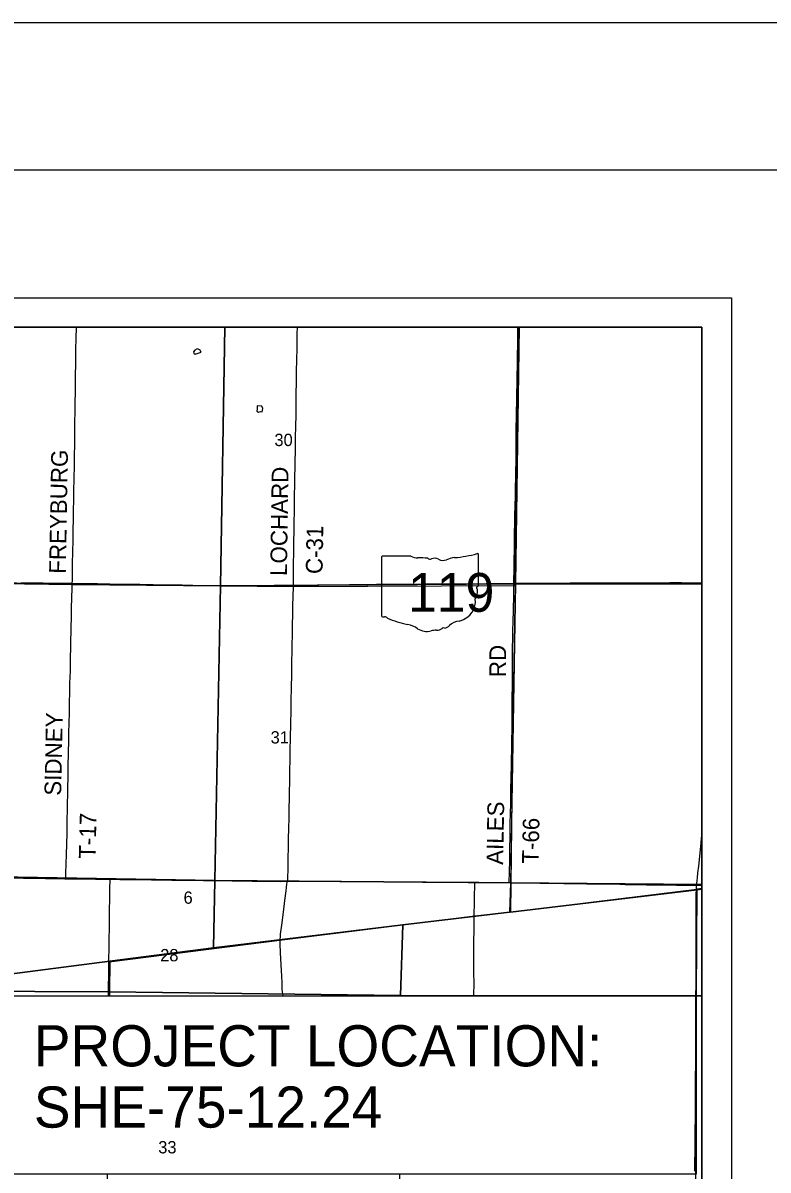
# Model space of a CAD drawing. Extents: x -784 to 1375, y -225 to 440.
# Drawn here: x 534 to 584.7, y 362 to 440 of the extents above; entities that cross this region are included whole.
import ezdxf

# ---------------------------------------------------------------- set-up
doc = ezdxf.new("R2010")
doc.units = 0
for name, color, linetype in [('GM_X_County_Road', 7, 'Continuous'), ('GM_X_County_Road_Text', 7, 'Continuous'), ('GM_X_Minor_Lake', 7, 'Continuous'), ('GM_X_Section', 7, 'Continuous'), ('GM_X_Section_Text', 7, 'Continuous'), ('GM_X_State_Location', 7, 'Continuous'), ('GM_X_State_Route', 7, 'Continuous'), ('GM_X_State_Shield', 7, 'Continuous'), ('GM_X_Township', 7, 'Continuous'), ('GM_X_Township_Road', 7, 'Continuous'), ('GM_X_Township_Road_Text', 7, 'Continuous'), ('SH_Border', 7, 'Continuous'), ('SH_Cut_Line', 7, 'Continuous'), ('SH_Data', 7, 'Continuous'), ('SH_Text', 7, 'Continuous')]:
    doc.layers.add(name, color=color, linetype=linetype)

msp = doc.modelspace()

# ---------------------------------------------------------------- linework, layer by layer
at = {"layer": 'GM_X_County_Road'}
for points in [[(552.435, 401.755), (552.433, 401.938), (552.43, 402.166), (552.431, 402.459), (552.441, 403.13), (552.456, 404.037), (552.467, 404.808), (552.476, 405.342), (552.488, 405.939), (552.499, 406.858), (552.505, 407.231), (552.513, 407.902), (552.525, 408.523), (552.532, 409.116), (552.542, 409.791), (552.554, 410.188), (552.564, 410.855), (552.567, 411.282), (552.58, 411.928), (552.59, 412.441), (552.606, 413.456), (552.613, 413.978), (552.627, 414.86), (552.633, 415.482), (552.641, 416.228), (552.646, 416.563), (552.653, 416.812), (552.663, 417.259), (552.674, 417.669), (552.676, 418.029), (552.689, 418.849), (552.699, 419.309)], [(579.873, 381.341), (579.883, 381.46), (579.906, 381.651), (579.922, 381.836), (579.963, 382.182), (580.011, 382.626), (580.154, 383.973), (580.212, 384.517), (580.236, 384.74)], [(539.873, 376.089), (539.876, 376.282), (539.883, 377.053), (539.89, 377.786), (539.902, 378.32), (539.911, 378.904), (539.92, 379.849), (539.927, 380.209), (539.942, 381.191), (539.948, 381.613), (539.95, 381.747)], [(579.851, 380.737), (579.857, 381.054), (579.87, 381.301), (579.873, 381.341)], [(579.873, 381.341), (580.236, 381.337)], [(579.752, 361.892), (579.753, 362.252), (579.756, 362.551), (579.766, 363.159), (579.768, 363.681), (579.781, 364.551), (579.789, 365.607), (579.789, 365.93), (579.791, 366.427), (579.796, 367.136), (579.798, 367.621), (579.803, 368.304), (579.808, 369.099), (579.811, 369.845), (579.813, 371.013), (579.812, 371.448), (579.823, 372.231), (579.829, 372.827), (579.826, 373.287), (579.829, 373.933), (579.83, 374.468), (579.838, 377.14), (579.837, 378.246), (579.835, 378.892), (579.836, 379.451), (579.85, 380.707), (579.851, 380.737)], [(539.845, 373.821), (539.849, 374.058), (539.865, 375.586), (539.873, 376.089)]]:
    msp.add_lwpolyline(points, dxfattribs=at)
at = {"layer": 'GM_X_Minor_Lake'}
for points in [[(545.718, 417.736), (545.636, 417.633), (545.65, 417.542), (545.74, 417.472), (546.014, 417.56)], [(546.014, 417.56), (546.152, 417.603), (546.07, 417.764), (545.874, 417.819), (545.718, 417.736)], [(549.952, 413.964), (549.96, 413.753), (549.933, 413.594), (550.046, 413.523), (550.207, 413.557), (550.307, 413.555)], [(550.307, 413.555), (550.357, 413.767), (550.269, 413.936), (549.952, 413.964)]]:
    msp.add_lwpolyline(points, dxfattribs=at)
at = {"layer": 'GM_X_Section'}
for p, q in [((547.764, 419.309), (527.74, 419.309)), ((567.795, 419.309), (547.764, 419.309)), ((580.236, 381.387), (580.236, 401.813)), ((580.236, 381.11), (580.236, 381.387)), ((580.236, 373.815), (580.236, 381.11)), ((580.236, 353.654), (580.236, 373.815))]:
    msp.add_line(p, q, dxfattribs=at)
for points in [[(527.74, 419.309), (527.384, 402), (547.468, 401.707), (547.764, 419.309)], [(547.764, 419.309), (547.468, 401.707), (567.552, 401.849), (567.795, 419.309)], [(567.795, 419.309), (567.552, 401.849), (580.236, 401.813)], [(580.236, 401.813), (580.236, 419.309), (567.795, 419.309)], [(580.236, 401.813), (567.552, 401.849), (567.193, 381.509), (580.236, 381.387)], [(580.236, 381.387), (567.193, 381.509), (567.128, 379.51), (579.896, 381.069), (580.236, 381.11)], [(580.236, 381.11), (579.896, 381.069), (579.839, 373.821), (580.236, 373.815)], [(539.743, 361.675), (539.64, 353.876), (519.562, 354.071), (519.776, 373.558), (524.658, 374.163), (539.907, 374.093), (539.903, 373.821)], [(539.903, 373.821), (539.907, 374.093), (559.72, 373.843), (559.72, 373.821)], [(559.72, 373.821), (559.72, 373.843), (579.839, 373.821), (579.739, 353.659), (559.644, 353.735), (559.674, 361.675)], [(580.236, 373.815), (579.839, 373.821), (579.739, 353.659), (580.236, 353.654)]]:
    msp.add_lwpolyline(points, dxfattribs=at)
for points in [[(527.384, 402), (547.468, 401.707), (547.078, 381.663), (526.941, 381.994)], [(547.468, 401.707), (567.552, 401.849), (567.193, 381.509), (547.078, 381.663)], [(526.941, 381.994), (547.078, 381.663), (546.992, 377.089), (539.93, 376.176), (526.778, 374.467)], [(547.078, 381.663), (567.193, 381.509), (567.128, 379.51), (559.879, 378.635), (546.992, 377.089)], [(567.128, 379.51), (579.896, 381.069), (579.839, 373.821), (559.72, 373.843), (559.879, 378.635)], [(546.992, 377.089), (559.879, 378.635), (559.72, 373.843), (539.907, 374.093), (539.93, 376.176)], [(526.778, 374.467), (539.93, 376.176), (539.907, 374.093), (524.658, 374.163)]]:
    msp.add_lwpolyline(points, close=True, dxfattribs=at)
at = {"layer": 'GM_X_State_Route'}
msp.add_lwpolyline([(533.933, 401.931), (535.4, 401.92), (537.214, 401.899), (537.374, 401.896), (539.103, 401.865), (540.78, 401.829), (541.973, 401.812), (543.8, 401.783), (544.856, 401.765), (545.589, 401.749), (547.204, 401.72), (549.429, 401.734), (550.423, 401.74), (551.119, 401.743), (552.435, 401.755), (552.622, 401.757), (554.064, 401.768), (554.86, 401.772), (556.251, 401.789), (557.556, 401.806), (558.078, 401.81), (559.669, 401.823), (561.446, 401.833), (562.987, 401.841), (564.105, 401.852), (565.547, 401.863), (565.882, 401.866), (567.431, 401.883), (567.553, 401.882), (567.668, 401.881), (567.991, 401.88), (568.438, 401.884), (568.835, 401.888), (569.768, 401.894), (570.414, 401.897), (571.259, 401.903), (571.545, 401.903), (571.83, 401.906), (572.29, 401.909), (573.148, 401.914), (573.744, 401.915), (574.254, 401.919), (574.639, 401.918), (575.211, 401.918), (575.77, 401.918), (576.689, 401.919), (577.1, 401.919), (577.733, 401.922), (578.044, 401.924), (578.852, 401.924), (579.771, 401.919), (580.236, 401.917)], dxfattribs=at)
at = {"layer": 'GM_X_State_Shield'}
for p, q in [((558.432, 403.663), (558.432, 399.661)), ((560.427, 403.732), (558.497, 403.732)), ((565.024, 401.737), (565.024, 403.831)), ((565.023, 401.738), (565.024, 401.737))]:
    msp.add_line(p, q, dxfattribs=at)
for centre, major_axis, start_param, end_param in [((558.508, 403.672), (0.0764, 0), 1.712693, 3.28349), ((560.887, 404.197), (0.741, 0), 4.042523, 4.731795), ((561.133, 401.485), (2.659, 0), 1.404758, 1.657858), ((561.736, 403.692), (0.214, 0), 3.836095, 5.185415), ((562.05, 403.23), (0.444, 0), 0.950623, 2.079405), ((562.623, 403.864), (0.534, 0), 4.081561, 5.145723), ((563.567, 402.509), (1.406, 0), 1.699011, 2.107814), ((562.676, 409.189), (6.99, 0), 4.814394, 5.042369), ((564.951, 403.84), (0.0734, 0), 6.141152, 7.989035), ((565.287, 400.861), (0.496, 0), 2.387724, 3.262537), ((565.007, 401.584), (0.114, 0), 1.883978, 3.671073), ((564.284, 401.319), (0.682, 0), 5.934695, 6.695948), ((564.945, 401.729), (0.0785, 0), 5.05454, 6.418171), ((563.067, 400.595), (1.748, 0), 5.101752, 6.440018), ((558.508, 399.652), (0.077, 0), 3.00124, 4.508301), ((558.52, 400.061), (0.588, 0), 4.665946, 4.897461), ((558.64, 399.43), (0.212, 0), 0.519207, 1.627899), ((561.317, 403.026), (5.048, 0), 4.195997, 4.488961), ((559.812, 397.863), (1.579, 0), 0.823519, 1.323587), ((561.52, 399.41), (1.002, 0), 4.026481, 4.996735), ((562.172, 399.11), (0.534, 0), 4.691044, 5.507374), ((562.655, 398.722), (0.15, 0), 1.147584, 2.315152), ((562.591, 399.273), (0.565, 0), 4.937069, 5.64225), ((563.804, 398.537), (0.958, 0), 1.647645, 2.488434), ((562.099, 398.026), (0.824, 0), 1.495662, 1.94098)]:
    msp.add_ellipse(centre, major_axis=major_axis, ratio=0.8, start_param=start_param, end_param=end_param, dxfattribs=at)
at = {"layer": 'GM_X_Township'}
msp.add_line((567.763, 419.309), (447.025, 419.309), dxfattribs=at)
for points in [[(447.025, 419.309), (446.855, 411.89), (446.652, 403.07), (467.059, 402.728), (492.276, 402.408), (492.603, 402.404), (493.649, 402.379), (495.222, 402.342), (497.28, 402.294), (498.869, 402.289), (499.79, 402.287), (508.769, 402.226), (510.045, 402.212), (511.496, 402.178), (514.371, 402.111), (537.416, 401.801), (552.453, 401.662), (567.523, 401.722), (567.763, 419.309)], [(567.763, 419.309), (567.523, 401.722), (567.34, 391.308), (567.235, 381.411), (567.213, 379.512), (579.899, 381.036), (580.236, 381.078)], [(580.236, 381.078), (580.236, 419.309), (567.763, 419.309)], [(492.603, 402.404), (493.649, 402.379), (495.222, 402.342), (497.28, 402.294), (499.79, 402.287), (508.769, 402.226), (510.045, 402.212), (511.496, 402.178), (514.371, 402.111), (537.416, 401.801), (552.453, 401.662), (567.523, 401.722), (567.34, 391.308), (567.235, 381.411), (567.213, 379.512), (564.776, 379.245), (551.839, 377.627), (539.885, 376.116), (539.861, 373.821)], [(580.236, 307.641), (580.236, 381.078), (579.899, 381.036), (567.213, 379.512), (564.776, 379.245), (551.839, 377.627), (539.885, 376.116), (539.861, 373.821)]]:
    msp.add_lwpolyline(points, dxfattribs=at)
at = {"layer": 'GM_X_Township_Road'}
for points in [[(537.374, 401.896), (537.382, 402.073), (537.395, 402.868), (537.403, 403.415), (537.407, 403.813), (537.433, 404.993), (537.459, 406.733), (537.474, 407.652), (537.483, 408.211), (537.5, 408.932), (537.523, 409.938), (537.533, 410.584), (537.543, 411.305), (537.551, 412.299), (537.554, 412.622), (537.561, 412.995), (537.567, 413.418), (537.577, 414.176), (537.586, 414.872), (537.599, 415.505), (537.607, 416.052), (537.615, 416.76), (537.618, 417.183), (537.631, 417.754), (537.647, 418.587), (537.658, 419.233), (537.66, 419.309)], [(567.431, 401.883), (567.437, 402.216), (567.449, 402.651), (567.464, 403.583), (567.466, 404.017), (567.469, 404.204), (567.481, 404.713), (567.481, 404.874), (567.476, 405.11), (567.481, 405.195), (567.482, 405.245), (567.485, 405.357), (567.494, 405.878), (567.508, 406.599), (567.514, 407.034), (567.535, 407.916), (567.539, 408.252), (567.558, 409.208), (567.583, 410.463), (567.585, 411.233), (567.584, 411.569), (567.588, 411.979), (567.592, 412.265), (567.596, 412.538), (567.61, 413.085), (567.64, 414.7), (567.653, 415.532), (567.663, 416.092), (567.671, 416.639), (567.679, 417.272), (567.698, 418.241), (567.71, 419.309)], [(536.949, 381.78), (536.948, 381.946), (536.948, 382.158), (536.984, 383.437), (537.022, 384.854), (537.038, 385.674), (537.057, 386.593), (537.08, 387.86), (537.092, 388.83), (537.108, 389.413), (537.125, 390.358), (537.142, 391.178), (537.149, 391.725), (537.165, 392.371), (537.183, 393.091), (537.189, 393.427), (537.195, 393.737), (537.21, 394.495), (537.222, 395.079), (537.246, 395.899), (537.258, 396.545), (537.284, 397.775), (537.301, 398.794), (537.319, 399.639), (537.333, 400.322), (537.342, 400.757), (537.366, 401.689), (537.372, 401.863), (537.374, 401.896)], [(552.02, 381.615), (552.039, 381.687), (552.049, 381.742), (552.054, 381.805), (552.056, 382.01), (552.062, 382.27), (552.07, 382.916), (552.08, 383.301), (552.088, 383.786), (552.104, 384.569), (552.116, 385.14), (552.135, 385.985), (552.146, 386.706), (552.156, 387.128), (552.169, 387.862), (552.175, 388.209), (552.178, 388.744), (552.19, 389.228), (552.201, 389.788), (552.208, 390.073), (552.211, 390.422), (552.217, 390.744), (552.229, 391.12), (552.237, 391.601), (552.249, 392.111), (552.258, 392.521), (552.269, 393.017), (552.281, 393.837), (552.286, 394.086), (552.293, 394.595), (552.317, 395.888), (552.325, 396.584), (552.34, 397.209), (552.346, 397.641), (552.352, 397.858), (552.359, 398.224), (552.373, 399.168), (552.38, 399.653), (552.391, 400.137), (552.396, 400.473), (552.404, 400.87), (552.435, 401.755)], [(567.302, 391.263), (567.305, 391.435), (567.313, 391.708), (567.316, 391.971), (567.32, 392.222), (567.323, 392.482), (567.328, 392.775), (567.322, 393.059), (567.322, 393.506), (567.326, 394.04), (567.338, 394.972), (567.341, 395.32), (567.349, 395.668), (567.351, 396.239), (567.347, 396.6), (567.348, 397.494), (567.354, 398.128), (567.362, 398.513), (567.396, 399.42), (567.404, 399.892), (567.424, 401.222), (567.429, 401.731), (567.431, 401.883)], [(567.115, 381.517), (567.119, 381.632), (567.133, 382.141), (567.148, 383.135), (567.158, 383.806), (567.175, 384.663), (567.191, 385.546), (567.205, 386.217), (567.221, 386.875), (567.231, 387.544), (567.233, 387.683), (567.257, 388.813), (567.27, 389.373), (567.279, 389.969), (567.289, 390.491), (567.292, 390.777), (567.302, 391.263)], [(521.896, 381.998), (522.823, 381.988), (523.78, 381.97), (525.121, 381.947), (525.805, 381.936), (526.898, 381.926), (527.829, 381.915), (529.022, 381.907), (529.954, 381.893), (530.787, 381.883), (531.47, 381.871), (532.079, 381.862), (532.961, 381.851), (533.682, 381.835), (534.055, 381.829), (534.378, 381.825), (535.558, 381.806), (536.353, 381.79), (536.863, 381.781), (536.949, 381.78)], [(536.949, 381.78), (537.347, 381.775), (537.707, 381.773), (538.242, 381.765), (538.95, 381.761), (539.95, 381.747)], [(539.95, 381.747), (540.156, 381.744), (540.615, 381.736), (541.1, 381.736), (541.559, 381.726), (541.994, 381.727), (542.777, 381.71), (543.212, 381.702), (543.87, 381.697), (544.144, 381.693), (544.628, 381.685), (545.001, 381.685), (545.722, 381.676), (546.318, 381.667), (546.728, 381.66), (547.324, 381.656), (547.647, 381.656), (548.256, 381.648), (548.579, 381.644), (549.138, 381.632), (549.611, 381.625), (550.008, 381.62), (550.754, 381.61), (551.561, 381.604), (552.02, 381.615)], [(551.532, 377.62), (551.532, 377.666), (551.541, 377.827), (551.561, 378.012), (551.649, 378.627), (551.755, 379.503), (551.849, 380.293), (551.927, 380.96), (551.951, 381.182), (551.982, 381.44), (552, 381.532), (552.02, 381.615)], [(552.02, 381.615), (552.319, 381.618), (552.615, 381.615), (552.996, 381.615), (553.404, 381.615), (554.431, 381.612), (554.978, 381.611), (555.599, 381.604), (556.009, 381.601), (556.332, 381.598), (556.842, 381.592), (557.128, 381.591), (557.5, 381.589), (558.196, 381.585), (558.892, 381.58), (559.588, 381.575), (560.359, 381.57), (561.216, 381.558), (561.95, 381.554), (562.633, 381.548), (562.919, 381.548), (564.584, 381.543), (564.775, 381.541)], [(564.733, 379.244), (564.737, 379.517), (564.746, 379.952), (564.756, 380.511), (564.772, 381.406), (564.775, 381.541)], [(564.775, 381.541), (565.044, 381.538), (565.715, 381.532), (566.473, 381.524), (567.115, 381.517)], [(567.115, 381.517), (567.219, 381.516), (567.815, 381.505), (568.412, 381.497), (569.207, 381.489), (569.854, 381.478), (570.823, 381.464), (571.581, 381.45), (571.917, 381.448), (572.376, 381.441), (573.395, 381.426), (574.65, 381.405), (575.011, 381.397), (575.519, 381.388), (575.9, 381.382), (576.452, 381.373), (576.921, 381.364), (577.232, 381.359), (577.76, 381.356), (578.506, 381.347), (579.249, 381.346), (579.754, 381.342), (579.873, 381.341)], [(564.717, 373.821), (564.72, 374.72), (564.718, 375.304), (564.715, 376.037), (564.713, 376.659), (564.714, 376.932), (564.715, 377.218), (564.725, 378.598), (564.727, 378.744)], [(564.727, 378.744), (564.733, 379.244)], [(551.537, 377.339), (551.533, 377.417), (551.532, 377.62)], [(551.723, 373.821), (551.702, 373.955), (551.686, 374.09), (551.674, 374.264), (551.654, 374.674), (551.635, 375.17), (551.621, 375.518), (551.603, 375.952), (551.582, 376.325), (551.559, 376.771), (551.537, 377.339)]]:
    msp.add_lwpolyline(points, dxfattribs=at)
at = {"layer": 'SH_Border'}
msp.add_lwpolyline([(30, 430), (670, 430), (670, 10), (30, 10)], close=True, dxfattribs=at)
at = {"layer": 'SH_Cut_Line'}
msp.add_lwpolyline([(0, 0), (680, 0), (680, 440), (0, 440)], close=True, dxfattribs=at)
at = {"layer": 'SH_Data'}
for p, q in [((442.236, 421.309), (582.236, 421.309)), ((582.236, 421.309), (582.236, 281.309)), ((444.236, 419.309), (580.236, 419.309)), ((580.236, 419.309), (580.236, 283.309))]:
    msp.add_line(p, q, dxfattribs=at)
at = {"layer": 'SH_Text'}
msp.add_lwpolyline([(532.832, 373.821), (579.839, 373.821), (579.839, 361.675), (532.832, 361.675)], close=True, dxfattribs=at)

# ---------------------------------------------------------------- texts
at = {"layer": 'GM_X_County_Road_Text'}
for s, rotation, p in [('LOCHARD', 89.15096, (551.986, 402.373)), ('C-31', 89.00333, (554.407, 402.501))]:
    msp.add_text(s, height=1.1364, rotation=rotation, dxfattribs=at).set_placement(p)
at = {"layer": 'GM_X_Section_Text'}
for s, height, p in [('30', 0.8371, (551.136, 411.216)), ('31', 0.8371, (550.878, 390.982)), ('6', 0.837, (544.953, 380.082)), ('28', 0.8371, (543.361, 376.166)), ('33', 0.8371, (543.228, 363.099))]:
    msp.add_text(s, height=height, rotation=0.00001, dxfattribs=at).set_placement(p)
at = {"layer": 'GM_X_State_Location'}
msp.add_text('119', height=0.00379, rotation=0.00001, dxfattribs=at).set_placement((560.317, 401.12))
for s in ['s', 'r']:
    msp.add_text(s, height=0.00379, dxfattribs=at).set_placement((561.654, 401.396))
at = {"layer": 'GM_X_State_Shield'}
msp.add_text('119', height=2.6367, dxfattribs=at).set_placement((560.221, 399.943))
at = {"layer": 'GM_X_Township_Road_Text'}
for s, rotation, p in [('FREYBURG', 88.97023, (536.936, 402.521)), ('RD', 90, (566.903, 395.498)), ('SIDNEY', 88.87637, (536.619, 387.422)), ('AILES', 89.02657, (566.703, 382.72)), ('T-17', 88.57534, (538.956, 383.124)), ('T-66', 88.96406, (569.122, 382.795))]:
    msp.add_text(s, height=1.1364, rotation=rotation, dxfattribs=at).set_placement(p)
at = {"layer": 'SH_Text'}
for s, p in [('PROJECT LOCATION:', (534.761, 369.017)), ('SHE-75-12.24', (534.761, 364.85))]:
    msp.add_text(s, height=2.8, dxfattribs=at).set_placement(p)

doc.saveas('drawing.dxf')
